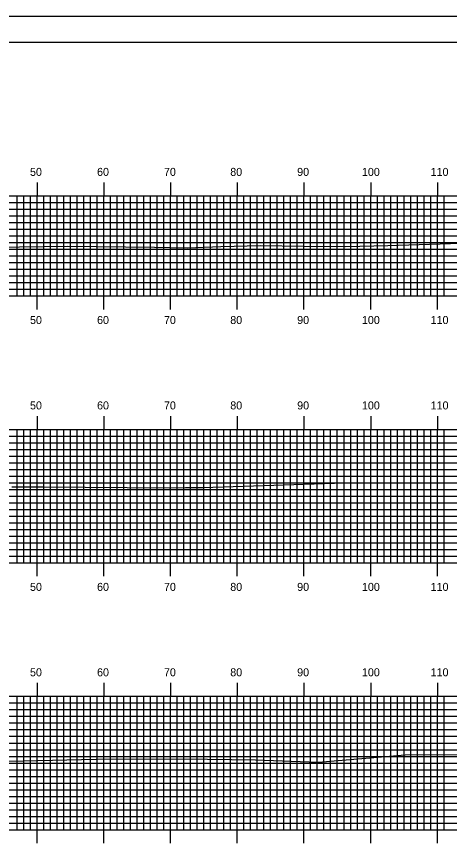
# Model space of a CAD drawing. Extents: x 1778319 to 1778662, y 442591 to 442811.
# Drawn here: x 1778531.2 to 1778596.1, y 442686.2 to 442810.5 of the extents above; entities that cross this region are included whole.
import ezdxf

# ---------------------------------------------------------------- set-up
doc = ezdxf.new("R2010")
doc.units = 0
for name, color, linetype in [('BORDER', 7, 'Continuous'), ('H_V ANNOTATION', 7, 'Continuous'), ('MAJOR', 7, 'Continuous'), ('MINOR', 7, 'Continuous'), ('PLOT BOUNDARY', 7, 'Continuous'), ('S_Roadway_Centerline', 7, 'Continuous')]:
    doc.layers.add(name, color=color, linetype=linetype)

msp = doc.modelspace()

# ---------------------------------------------------------------- linework, layer by layer
at = {"layer": 'BORDER'}
msp.add_lwpolyline([(1778334.7, 442596.67), (1778654.7, 442596.67), (1778654.7, 442806.67), (1778334.7, 442806.67)], close=True, dxfattribs=at)
at = {"layer": 'MAJOR'}
for p, q in [((1778534.3, 442785.67), (1778534.3, 442783.67)), ((1778544.3, 442785.67), (1778544.3, 442783.67)), ((1778554.3, 442785.67), (1778554.3, 442783.67)), ((1778564.3, 442785.67), (1778564.3, 442783.67)), ((1778574.3, 442785.67), (1778574.3, 442783.67)), ((1778584.3, 442785.67), (1778584.3, 442783.67)), ((1778594.3, 442785.67), (1778594.3, 442783.67)), ((1778344.3, 442783.67), (1778624.3, 442783.67)), ((1778344.3, 442783.67), (1778624.3, 442783.67)), ((1778534.3, 442768.67), (1778534.3, 442783.67)), ((1778544.3, 442768.67), (1778544.3, 442783.67)), ((1778554.3, 442768.67), (1778554.3, 442783.67)), ((1778564.3, 442768.67), (1778564.3, 442783.67)), ((1778574.3, 442768.67), (1778574.3, 442783.67)), ((1778584.3, 442768.67), (1778584.3, 442783.67)), ((1778594.3, 442768.67), (1778594.3, 442783.67)), ((1778344.3, 442778.67), (1778624.3, 442778.67)), ((1778344.3, 442773.67), (1778624.3, 442773.67)), ((1778344.3, 442768.67), (1778624.3, 442768.67)), ((1778344.3, 442768.67), (1778624.3, 442768.67)), ((1778534.3, 442766.66), (1778534.3, 442768.67)), ((1778544.3, 442766.66), (1778544.3, 442768.67)), ((1778554.3, 442766.66), (1778554.3, 442768.67)), ((1778564.3, 442766.66), (1778564.3, 442768.67)), ((1778574.3, 442766.66), (1778574.3, 442768.67)), ((1778584.3, 442766.66), (1778584.3, 442768.67)), ((1778594.3, 442766.66), (1778594.3, 442768.67)), ((1778534.3, 442750.67), (1778534.3, 442748.67)), ((1778544.3, 442750.67), (1778544.3, 442748.67)), ((1778554.3, 442750.67), (1778554.3, 442748.67)), ((1778564.3, 442750.67), (1778564.3, 442748.67)), ((1778574.3, 442750.67), (1778574.3, 442748.67)), ((1778584.3, 442750.67), (1778584.3, 442748.67)), ((1778594.3, 442750.67), (1778594.3, 442748.67)), ((1778344.3, 442748.67), (1778624.3, 442748.67)), ((1778344.3, 442748.67), (1778624.3, 442748.67)), ((1778534.3, 442728.67), (1778534.3, 442748.67)), ((1778544.3, 442728.67), (1778544.3, 442748.67)), ((1778554.3, 442728.67), (1778554.3, 442748.67)), ((1778564.3, 442728.67), (1778564.3, 442748.67)), ((1778574.3, 442728.67), (1778574.3, 442748.67)), ((1778584.3, 442728.67), (1778584.3, 442748.67)), ((1778594.3, 442728.67), (1778594.3, 442748.67)), ((1778344.3, 442743.67), (1778624.3, 442743.67)), ((1778344.3, 442738.67), (1778624.3, 442738.67)), ((1778344.3, 442733.67), (1778624.3, 442733.67)), ((1778344.3, 442728.67), (1778624.3, 442728.67)), ((1778344.3, 442728.67), (1778624.3, 442728.67)), ((1778534.3, 442726.66), (1778534.3, 442728.67)), ((1778544.3, 442726.66), (1778544.3, 442728.67)), ((1778554.3, 442726.66), (1778554.3, 442728.67)), ((1778564.3, 442726.66), (1778564.3, 442728.67)), ((1778574.3, 442726.66), (1778574.3, 442728.67)), ((1778584.3, 442726.66), (1778584.3, 442728.67)), ((1778594.3, 442726.66), (1778594.3, 442728.67)), ((1778534.3, 442710.67), (1778534.3, 442708.67)), ((1778544.3, 442710.67), (1778544.3, 442708.67)), ((1778554.3, 442710.67), (1778554.3, 442708.67)), ((1778564.3, 442710.67), (1778564.3, 442708.67)), ((1778574.3, 442710.67), (1778574.3, 442708.67)), ((1778584.3, 442710.67), (1778584.3, 442708.67)), ((1778594.3, 442710.67), (1778594.3, 442708.67)), ((1778344.3, 442708.67), (1778624.3, 442708.67)), ((1778344.3, 442708.67), (1778624.3, 442708.67)), ((1778534.3, 442688.67), (1778534.3, 442708.67)), ((1778544.3, 442688.67), (1778544.3, 442708.67)), ((1778554.3, 442688.67), (1778554.3, 442708.67)), ((1778564.3, 442688.67), (1778564.3, 442708.67)), ((1778574.3, 442688.67), (1778574.3, 442708.67)), ((1778584.3, 442688.67), (1778584.3, 442708.67)), ((1778594.3, 442688.67), (1778594.3, 442708.67)), ((1778344.3, 442703.67), (1778624.3, 442703.67)), ((1778344.3, 442698.67), (1778624.3, 442698.67)), ((1778344.3, 442693.67), (1778624.3, 442693.67)), ((1778344.3, 442688.67), (1778624.3, 442688.67)), ((1778344.3, 442688.67), (1778624.3, 442688.67)), ((1778534.3, 442686.66), (1778534.3, 442688.67)), ((1778544.3, 442686.66), (1778544.3, 442688.67)), ((1778554.3, 442686.66), (1778554.3, 442688.67)), ((1778564.3, 442686.66), (1778564.3, 442688.67)), ((1778574.3, 442686.66), (1778574.3, 442688.67)), ((1778584.3, 442686.66), (1778584.3, 442688.67)), ((1778594.3, 442686.66), (1778594.3, 442688.67))]:
    msp.add_line(p, q, dxfattribs=at)
at = {"layer": 'MINOR'}
for p, q in [((1778531.3, 442768.67), (1778531.3, 442783.67)), ((1778532.3, 442768.67), (1778532.3, 442783.67)), ((1778533.3, 442768.67), (1778533.3, 442783.67)), ((1778535.3, 442768.67), (1778535.3, 442783.67)), ((1778536.3, 442768.67), (1778536.3, 442783.67)), ((1778537.3, 442768.67), (1778537.3, 442783.67)), ((1778538.3, 442768.67), (1778538.3, 442783.67)), ((1778539.3, 442768.67), (1778539.3, 442783.67)), ((1778540.3, 442768.67), (1778540.3, 442783.67)), ((1778541.3, 442768.67), (1778541.3, 442783.67)), ((1778542.3, 442768.67), (1778542.3, 442783.67)), ((1778543.3, 442768.67), (1778543.3, 442783.67)), ((1778545.3, 442768.67), (1778545.3, 442783.67)), ((1778546.3, 442768.67), (1778546.3, 442783.67)), ((1778547.3, 442768.67), (1778547.3, 442783.67)), ((1778548.3, 442768.67), (1778548.3, 442783.67)), ((1778549.3, 442768.67), (1778549.3, 442783.67)), ((1778550.3, 442768.67), (1778550.3, 442783.67)), ((1778551.3, 442768.67), (1778551.3, 442783.67)), ((1778552.3, 442768.67), (1778552.3, 442783.67)), ((1778553.3, 442768.67), (1778553.3, 442783.67)), ((1778555.3, 442768.67), (1778555.3, 442783.67)), ((1778556.3, 442768.67), (1778556.3, 442783.67)), ((1778557.3, 442768.67), (1778557.3, 442783.67)), ((1778558.3, 442768.67), (1778558.3, 442783.67)), ((1778559.3, 442768.67), (1778559.3, 442783.67)), ((1778560.3, 442768.67), (1778560.3, 442783.67)), ((1778561.3, 442768.67), (1778561.3, 442783.67)), ((1778562.3, 442768.67), (1778562.3, 442783.67)), ((1778563.3, 442768.67), (1778563.3, 442783.67)), ((1778565.3, 442768.67), (1778565.3, 442783.67)), ((1778566.3, 442768.67), (1778566.3, 442783.67)), ((1778567.3, 442768.67), (1778567.3, 442783.67)), ((1778568.3, 442768.67), (1778568.3, 442783.67)), ((1778569.3, 442768.67), (1778569.3, 442783.67)), ((1778570.3, 442768.67), (1778570.3, 442783.67)), ((1778571.3, 442768.67), (1778571.3, 442783.67)), ((1778572.3, 442768.67), (1778572.3, 442783.67)), ((1778573.3, 442768.67), (1778573.3, 442783.67)), ((1778575.3, 442768.67), (1778575.3, 442783.67)), ((1778576.3, 442768.67), (1778576.3, 442783.67)), ((1778577.3, 442768.67), (1778577.3, 442783.67)), ((1778578.3, 442768.67), (1778578.3, 442783.67)), ((1778579.3, 442768.67), (1778579.3, 442783.67)), ((1778580.3, 442768.67), (1778580.3, 442783.67)), ((1778581.3, 442768.67), (1778581.3, 442783.67)), ((1778582.3, 442768.67), (1778582.3, 442783.67)), ((1778583.3, 442768.67), (1778583.3, 442783.67)), ((1778585.3, 442768.67), (1778585.3, 442783.67)), ((1778586.3, 442768.67), (1778586.3, 442783.67)), ((1778587.3, 442768.67), (1778587.3, 442783.67)), ((1778588.3, 442768.67), (1778588.3, 442783.67)), ((1778589.3, 442768.67), (1778589.3, 442783.67)), ((1778590.3, 442768.67), (1778590.3, 442783.67)), ((1778591.3, 442768.67), (1778591.3, 442783.67)), ((1778592.3, 442768.67), (1778592.3, 442783.67)), ((1778593.3, 442768.67), (1778593.3, 442783.67)), ((1778595.3, 442768.67), (1778595.3, 442783.67)), ((1778344.3, 442782.67), (1778624.3, 442782.67)), ((1778344.3, 442781.67), (1778624.3, 442781.67)), ((1778344.3, 442780.67), (1778624.3, 442780.67)), ((1778344.3, 442779.67), (1778624.3, 442779.67)), ((1778344.3, 442777.67), (1778624.3, 442777.67)), ((1778344.3, 442776.67), (1778624.3, 442776.67)), ((1778344.3, 442775.67), (1778624.3, 442775.67)), ((1778344.3, 442774.67), (1778624.3, 442774.67)), ((1778344.3, 442772.67), (1778624.3, 442772.67)), ((1778344.3, 442771.67), (1778624.3, 442771.67)), ((1778344.3, 442770.67), (1778624.3, 442770.67)), ((1778344.3, 442769.67), (1778624.3, 442769.67)), ((1778531.3, 442728.67), (1778531.3, 442748.67)), ((1778532.3, 442728.67), (1778532.3, 442748.67)), ((1778533.3, 442728.67), (1778533.3, 442748.67)), ((1778535.3, 442728.67), (1778535.3, 442748.67)), ((1778536.3, 442728.67), (1778536.3, 442748.67)), ((1778537.3, 442728.67), (1778537.3, 442748.67)), ((1778538.3, 442728.67), (1778538.3, 442748.67)), ((1778539.3, 442728.67), (1778539.3, 442748.67)), ((1778540.3, 442728.67), (1778540.3, 442748.67)), ((1778541.3, 442728.67), (1778541.3, 442748.67)), ((1778542.3, 442728.67), (1778542.3, 442748.67)), ((1778543.3, 442728.67), (1778543.3, 442748.67)), ((1778545.3, 442728.67), (1778545.3, 442748.67)), ((1778546.3, 442728.67), (1778546.3, 442748.67)), ((1778547.3, 442728.67), (1778547.3, 442748.67)), ((1778548.3, 442728.67), (1778548.3, 442748.67)), ((1778549.3, 442728.67), (1778549.3, 442748.67)), ((1778550.3, 442728.67), (1778550.3, 442748.67)), ((1778551.3, 442728.67), (1778551.3, 442748.67)), ((1778552.3, 442728.67), (1778552.3, 442748.67)), ((1778553.3, 442728.67), (1778553.3, 442748.67)), ((1778555.3, 442728.67), (1778555.3, 442748.67)), ((1778556.3, 442728.67), (1778556.3, 442748.67)), ((1778557.3, 442728.67), (1778557.3, 442748.67)), ((1778558.3, 442728.67), (1778558.3, 442748.67)), ((1778559.3, 442728.67), (1778559.3, 442748.67)), ((1778560.3, 442728.67), (1778560.3, 442748.67)), ((1778561.3, 442728.67), (1778561.3, 442748.67)), ((1778562.3, 442728.67), (1778562.3, 442748.67)), ((1778563.3, 442728.67), (1778563.3, 442748.67)), ((1778565.3, 442728.67), (1778565.3, 442748.67)), ((1778566.3, 442728.67), (1778566.3, 442748.67)), ((1778567.3, 442728.67), (1778567.3, 442748.67)), ((1778568.3, 442728.67), (1778568.3, 442748.67)), ((1778569.3, 442728.67), (1778569.3, 442748.67)), ((1778570.3, 442728.67), (1778570.3, 442748.67)), ((1778571.3, 442728.67), (1778571.3, 442748.67)), ((1778572.3, 442728.67), (1778572.3, 442748.67)), ((1778573.3, 442728.67), (1778573.3, 442748.67)), ((1778575.3, 442728.67), (1778575.3, 442748.67)), ((1778576.3, 442728.67), (1778576.3, 442748.67)), ((1778577.3, 442728.67), (1778577.3, 442748.67)), ((1778578.3, 442728.67), (1778578.3, 442748.67)), ((1778579.3, 442728.67), (1778579.3, 442748.67)), ((1778580.3, 442728.67), (1778580.3, 442748.67)), ((1778581.3, 442728.67), (1778581.3, 442748.67)), ((1778582.3, 442728.67), (1778582.3, 442748.67)), ((1778583.3, 442728.67), (1778583.3, 442748.67)), ((1778585.3, 442728.67), (1778585.3, 442748.67)), ((1778586.3, 442728.67), (1778586.3, 442748.67)), ((1778587.3, 442728.67), (1778587.3, 442748.67)), ((1778588.3, 442728.67), (1778588.3, 442748.67)), ((1778589.3, 442728.67), (1778589.3, 442748.67)), ((1778590.3, 442728.67), (1778590.3, 442748.67)), ((1778591.3, 442728.67), (1778591.3, 442748.67)), ((1778592.3, 442728.67), (1778592.3, 442748.67)), ((1778593.3, 442728.67), (1778593.3, 442748.67)), ((1778595.3, 442728.67), (1778595.3, 442748.67)), ((1778344.3, 442747.67), (1778624.3, 442747.67)), ((1778344.3, 442746.67), (1778624.3, 442746.67)), ((1778344.3, 442745.67), (1778624.3, 442745.67)), ((1778344.3, 442744.67), (1778624.3, 442744.67)), ((1778344.3, 442742.67), (1778624.3, 442742.67)), ((1778344.3, 442741.67), (1778624.3, 442741.67)), ((1778344.3, 442740.67), (1778624.3, 442740.67)), ((1778344.3, 442739.67), (1778624.3, 442739.67)), ((1778344.3, 442737.67), (1778624.3, 442737.67)), ((1778344.3, 442736.67), (1778624.3, 442736.67)), ((1778344.3, 442735.67), (1778624.3, 442735.67)), ((1778344.3, 442734.67), (1778624.3, 442734.67)), ((1778344.3, 442732.67), (1778624.3, 442732.67)), ((1778344.3, 442731.67), (1778624.3, 442731.67)), ((1778344.3, 442730.67), (1778624.3, 442730.67)), ((1778344.3, 442729.67), (1778624.3, 442729.67)), ((1778531.3, 442688.67), (1778531.3, 442708.67)), ((1778532.3, 442688.67), (1778532.3, 442708.67)), ((1778533.3, 442688.67), (1778533.3, 442708.67)), ((1778535.3, 442688.67), (1778535.3, 442708.67)), ((1778536.3, 442688.67), (1778536.3, 442708.67)), ((1778537.3, 442688.67), (1778537.3, 442708.67)), ((1778538.3, 442688.67), (1778538.3, 442708.67)), ((1778539.3, 442688.67), (1778539.3, 442708.67)), ((1778540.3, 442688.67), (1778540.3, 442708.67)), ((1778541.3, 442688.67), (1778541.3, 442708.67)), ((1778542.3, 442688.67), (1778542.3, 442708.67)), ((1778543.3, 442688.67), (1778543.3, 442708.67)), ((1778545.3, 442688.67), (1778545.3, 442708.67)), ((1778546.3, 442688.67), (1778546.3, 442708.67)), ((1778547.3, 442688.67), (1778547.3, 442708.67)), ((1778548.3, 442688.67), (1778548.3, 442708.67)), ((1778549.3, 442688.67), (1778549.3, 442708.67)), ((1778550.3, 442688.67), (1778550.3, 442708.67)), ((1778551.3, 442688.67), (1778551.3, 442708.67)), ((1778552.3, 442688.67), (1778552.3, 442708.67)), ((1778553.3, 442688.67), (1778553.3, 442708.67)), ((1778555.3, 442688.67), (1778555.3, 442708.67)), ((1778556.3, 442688.67), (1778556.3, 442708.67)), ((1778557.3, 442688.67), (1778557.3, 442708.67)), ((1778558.3, 442688.67), (1778558.3, 442708.67)), ((1778559.3, 442688.67), (1778559.3, 442708.67)), ((1778560.3, 442688.67), (1778560.3, 442708.67)), ((1778561.3, 442688.67), (1778561.3, 442708.67)), ((1778562.3, 442688.67), (1778562.3, 442708.67)), ((1778563.3, 442688.67), (1778563.3, 442708.67)), ((1778565.3, 442688.67), (1778565.3, 442708.67)), ((1778566.3, 442688.67), (1778566.3, 442708.67)), ((1778567.3, 442688.67), (1778567.3, 442708.67)), ((1778568.3, 442688.67), (1778568.3, 442708.67)), ((1778569.3, 442688.67), (1778569.3, 442708.67)), ((1778570.3, 442688.67), (1778570.3, 442708.67)), ((1778571.3, 442688.67), (1778571.3, 442708.67)), ((1778572.3, 442688.67), (1778572.3, 442708.67)), ((1778573.3, 442688.67), (1778573.3, 442708.67)), ((1778575.3, 442688.67), (1778575.3, 442708.67)), ((1778576.3, 442688.67), (1778576.3, 442708.67)), ((1778577.3, 442688.67), (1778577.3, 442708.67)), ((1778578.3, 442688.67), (1778578.3, 442708.67)), ((1778579.3, 442688.67), (1778579.3, 442708.67)), ((1778580.3, 442688.67), (1778580.3, 442708.67)), ((1778581.3, 442688.67), (1778581.3, 442708.67)), ((1778582.3, 442688.67), (1778582.3, 442708.67)), ((1778583.3, 442688.67), (1778583.3, 442708.67)), ((1778585.3, 442688.67), (1778585.3, 442708.67)), ((1778586.3, 442688.67), (1778586.3, 442708.67)), ((1778587.3, 442688.67), (1778587.3, 442708.67)), ((1778588.3, 442688.67), (1778588.3, 442708.67)), ((1778589.3, 442688.67), (1778589.3, 442708.67)), ((1778590.3, 442688.67), (1778590.3, 442708.67)), ((1778591.3, 442688.67), (1778591.3, 442708.67)), ((1778592.3, 442688.67), (1778592.3, 442708.67)), ((1778593.3, 442688.67), (1778593.3, 442708.67)), ((1778595.3, 442688.67), (1778595.3, 442708.67)), ((1778344.3, 442707.67), (1778624.3, 442707.67)), ((1778344.3, 442706.67), (1778624.3, 442706.67)), ((1778344.3, 442705.67), (1778624.3, 442705.67)), ((1778344.3, 442704.67), (1778624.3, 442704.67)), ((1778344.3, 442702.67), (1778624.3, 442702.67)), ((1778344.3, 442701.67), (1778624.3, 442701.67)), ((1778344.3, 442700.67), (1778624.3, 442700.67)), ((1778344.3, 442699.67), (1778624.3, 442699.67)), ((1778344.3, 442697.67), (1778624.3, 442697.67)), ((1778344.3, 442696.67), (1778624.3, 442696.67)), ((1778344.3, 442695.67), (1778624.3, 442695.67)), ((1778344.3, 442694.67), (1778624.3, 442694.67)), ((1778344.3, 442692.67), (1778624.3, 442692.67)), ((1778344.3, 442691.67), (1778624.3, 442691.67)), ((1778344.3, 442690.67), (1778624.3, 442690.67)), ((1778344.3, 442689.67), (1778624.3, 442689.67))]:
    msp.add_line(p, q, dxfattribs=at)
at = {"layer": 'PLOT BOUNDARY'}
msp.add_lwpolyline([(1778318.52, 442590.55), (1778658.52, 442590.55), (1778658.52, 442810.55), (1778318.52, 442810.55)], close=True, dxfattribs=at)
at = {"layer": 'S_Roadway_Centerline'}
for points in [[(1778528.07, 442776.01), (1778538.8, 442776.13), (1778551.87, 442776), (1778556.86, 442775.88), (1778561.83, 442776.07), (1778567.78, 442776.24), (1778574.21, 442776.16), (1778580.55, 442776.07), (1778586.85, 442776.22), (1778596.28, 442776.52), (1778611.8, 442776.7), (1778614.97, 442776.71), (1778618.4, 442776.67), (1778624.3, 442776.67)], [(1778530.49, 442740.05), (1778535.14, 442740.07), (1778554.16, 442739.94), (1778556.52, 442739.99), (1778559.16, 442739.98), (1778578.87, 442740.6), (1778598.92, 442740.73), (1778601.89, 442740.76), (1778605.03, 442740.97), (1778614.23, 442741.14), (1778624.3, 442740.8)], [(1778512.92, 442698.95), (1778532.18, 442699), (1778543.16, 442699.23), (1778556.26, 442699.3), (1778567.01, 442699.15), (1778576.41, 442698.8), (1778577.1, 442698.83), (1778589.45, 442699.9), (1778600.34, 442699.95), (1778612.59, 442699.79), (1778623.89, 442699.48), (1778624.3, 442699.48)]]:
    msp.add_lwpolyline(points, dxfattribs=at)

# ---------------------------------------------------------------- texts
at = {"layer": 'H_V ANNOTATION'}
for s, p in [('50', (1778533.23, 442786.67)), ('60', (1778543.28, 442786.67)), ('70', (1778553.31, 442786.67)), ('80', (1778563.25, 442786.67)), ('90', (1778573.28, 442786.67)), ('100', (1778582.99, 442786.67)), ('110', (1778593.29, 442786.67)), ('50', (1778533.23, 442764.47)), ('60', (1778543.28, 442764.47)), ('70', (1778553.31, 442764.47)), ('80', (1778563.25, 442764.47)), ('90', (1778573.28, 442764.47)), ('100', (1778582.99, 442764.47)), ('110', (1778593.29, 442764.47)), ('50', (1778533.23, 442751.67)), ('60', (1778543.28, 442751.67)), ('70', (1778553.31, 442751.67)), ('80', (1778563.25, 442751.67)), ('90', (1778573.28, 442751.67)), ('100', (1778582.99, 442751.67)), ('110', (1778593.29, 442751.67)), ('50', (1778533.23, 442724.47)), ('60', (1778543.28, 442724.47)), ('70', (1778553.31, 442724.47)), ('80', (1778563.25, 442724.47)), ('90', (1778573.28, 442724.47)), ('100', (1778582.99, 442724.47)), ('110', (1778593.29, 442724.47)), ('50', (1778533.23, 442711.67)), ('60', (1778543.28, 442711.67)), ('70', (1778553.31, 442711.67)), ('80', (1778563.25, 442711.67)), ('90', (1778573.28, 442711.67)), ('100', (1778582.99, 442711.67)), ('110', (1778593.29, 442711.67))]:
    msp.add_text(s, height=1.2, dxfattribs=at).set_placement(p)

doc.saveas('drawing.dxf')
